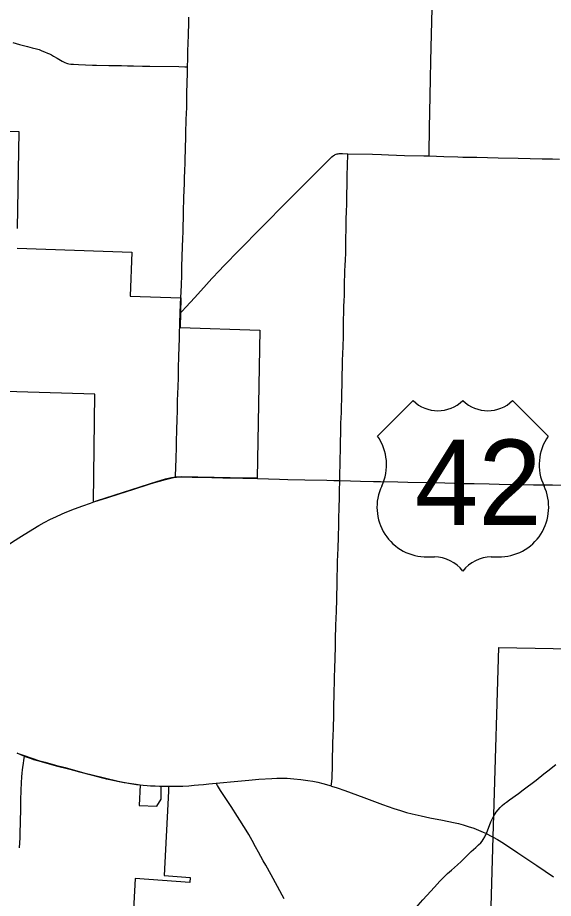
# Model space of a CAD drawing. Extents: x 9078 to 9739, y 4248 to 4966.
# Drawn here: x 9404.5 to 9448.2, y 4627.8 to 4699.7 of the extents above; entities that cross this region are included whole.
import ezdxf

# ---------------------------------------------------------------- set-up
doc = ezdxf.new("R2010")
doc.units = 0
for name, color, linetype in [('GM_X_City_Street', 7, 'Continuous'), ('GM_X_Corporation', 7, 'Continuous'), ('GM_X_County_Road', 7, 'Continuous'), ('GM_X_State_Route', 7, 'Continuous'), ('GM_X_Township', 7, 'Continuous'), ('GM_X_Township_Road', 7, 'Continuous'), ('GM_X_US_Route', 7, 'Continuous'), ('GM_X_US_Shield', 7, 'Continuous')]:
    doc.layers.add(name, color=color, linetype=linetype)

msp = doc.modelspace()

# ---------------------------------------------------------------- linework, layer by layer
at = {"layer": 'GM_X_City_Street'}
for points in [[(9417.378, 4662.149), (9417.388, 4662.384), (9417.402, 4662.847), (9417.411, 4663.16), (9417.421, 4663.477), (9417.431, 4663.815), (9417.448, 4664.48), (9417.453, 4664.688), (9417.463, 4665.075), (9417.486, 4665.984), (9417.512, 4666.884), (9417.532, 4667.539), (9417.553, 4668.439), (9417.566, 4668.93), (9417.609, 4670.239), (9417.626, 4671.058), (9417.653, 4672.04), (9417.669, 4672.777), (9417.693, 4673.513), (9417.711, 4674.167), (9417.72, 4674.388)], [(9404.66, 4631.906), (9404.678, 4632.316), (9404.694, 4632.727), (9404.711, 4633.298), (9404.726, 4633.827), (9404.73, 4634.009), (9404.755, 4635.112), (9404.771, 4635.759), (9404.794, 4636.679), (9404.798, 4636.835), (9404.809, 4636.996), (9404.819, 4637.244), (9404.85, 4637.669), (9404.878, 4638.046), (9404.899, 4638.251), (9404.924, 4638.502), (9404.965, 4638.784), (9405.008, 4639.056), (9405.032, 4639.196), (9405.067, 4639.389)]]:
    msp.add_lwpolyline(points, dxfattribs=at)
at = {"layer": 'GM_X_Corporation'}
for points in [[(9401.571, 4690.474), (9404.598, 4690.369), (9404.461, 4682.443)], [(9404.465, 4680.839), (9413.813, 4680.513), (9413.689, 4676.92), (9417.821, 4676.783), (9417.762, 4674.377), (9424.246, 4674.166), (9424.037, 4662.069), (9423.175, 4662.086), (9419.208, 4662.168), (9417.867, 4662.195), (9417.396, 4662.168), (9417.049, 4662.112), (9416.532, 4661.992), (9416.104, 4661.867), (9415.911, 4661.805), (9410.893, 4660.196), (9410.69, 4660.131), (9410.796, 4668.935), (9402.586, 4669.192)], [(9404.457, 4639.651), (9405.029, 4639.453), (9406.199, 4639.035), (9406.745, 4638.894), (9407.577, 4638.664), (9408.389, 4638.475), (9409.892, 4638.035), (9410.577, 4637.873), (9412.688, 4637.353), (9413.544, 4637.188), (9414.205, 4637.081), (9414.489, 4637.059), (9414.401, 4635.358), (9415.857, 4635.307), (9416.212, 4635.897), (9416.209, 4636.925), (9416.802, 4636.949), (9416.811, 4636.541), (9416.451, 4629.651), (9418.561, 4629.504), (9418.553, 4629.094), (9414.09, 4629.406), (9413.717, 4622.275)]]:
    msp.add_lwpolyline(points, dxfattribs=at)
at = {"layer": 'GM_X_County_Road'}
for points in [[(9438.067, 4688.371), (9438.071, 4688.605), (9438.105, 4690.65), (9438.15, 4693.268), (9438.169, 4694.659), (9438.204, 4696.131), (9438.328, 4701.524)], [(9418.362, 4695.648), (9418.362, 4695.684), (9418.378, 4696.258), (9418.394, 4696.913), (9418.409, 4697.568), (9418.428, 4698.223), (9418.438, 4698.551), (9418.451, 4698.96), (9418.472, 4699.696)], [(9417.814, 4676.793), (9417.856, 4677.821), (9417.882, 4678.641), (9417.9, 4679.297), (9417.929, 4680.197), (9417.975, 4681.673), (9417.991, 4682.165), (9418.008, 4682.738), (9418.022, 4683.23), (9418.031, 4683.737), (9418.036, 4684.223), (9418.044, 4684.553), (9418.051, 4684.818), (9418.061, 4685.039), (9418.074, 4685.508), (9418.105, 4686.178), (9418.121, 4686.67), (9418.135, 4687.08), (9418.161, 4687.899), (9418.195, 4689.129), (9418.213, 4689.784), (9418.232, 4690.44), (9418.252, 4691.096), (9418.26, 4691.423), (9418.269, 4691.751), (9418.288, 4692.405), (9418.3, 4692.815), (9418.309, 4693.553), (9418.329, 4694.291), (9418.353, 4695.192), (9418.362, 4695.648)], [(9417.766, 4675.549), (9417.889, 4675.679), (9418.256, 4676.064), (9418.917, 4676.793), (9419.689, 4677.644), (9420.352, 4678.371), (9420.961, 4679.035), (9421.301, 4679.391), (9421.705, 4679.799), (9422.227, 4680.321), (9422.686, 4680.789), (9423.203, 4681.316), (9423.775, 4681.902), (9424.582, 4682.716), (9425.096, 4683.244), (9425.843, 4684.006), (9426.48, 4684.645), (9427.119, 4685.281), (9427.98, 4686.159), (9428.851, 4687.028), (9430.016, 4688.183), (9430.137, 4688.296), (9430.267, 4688.4), (9430.338, 4688.445), (9430.413, 4688.484), (9430.49, 4688.516), (9430.571, 4688.539), (9430.654, 4688.555), (9430.737, 4688.564), (9430.986, 4688.571), (9431.442, 4688.559)], [(9431.442, 4688.559), (9433.445, 4688.507), (9434.183, 4688.48), (9434.756, 4688.454), (9435.411, 4688.437), (9436.067, 4688.419), (9437.625, 4688.385), (9438.067, 4688.371)], [(9438.067, 4688.371), (9439.264, 4688.334), (9440.412, 4688.29), (9440.821, 4688.277), (9441.969, 4688.263), (9443.691, 4688.218), (9445.331, 4688.181), (9447.299, 4688.149), (9448.118, 4688.127), (9448.692, 4688.118)], [(9417.766, 4675.549), (9417.796, 4676.305), (9417.814, 4676.793)], [(9417.72, 4674.388), (9417.741, 4674.918), (9417.76, 4675.407), (9417.766, 4675.549)], [(9444.377, 4635.653), (9444.613, 4635.833), (9445.345, 4636.363), (9445.743, 4636.652), (9446.07, 4636.898), (9446.458, 4637.198), (9446.784, 4637.447), (9447.432, 4637.952), (9447.754, 4638.206), (9448.404, 4638.706)], [(9443.352, 4634.532), (9443.441, 4634.685), (9443.534, 4634.822), (9443.688, 4635.017), (9443.854, 4635.201), (9444.032, 4635.374), (9444.22, 4635.534), (9444.377, 4635.653)], [(9442.735, 4633.077), (9443.103, 4634.025), (9443.204, 4634.251), (9443.316, 4634.471), (9443.352, 4634.532)]]:
    msp.add_lwpolyline(points, dxfattribs=at)
at = {"layer": 'GM_X_State_Route'}
for points in [[(9404.443, 4639.66), (9404.742, 4639.522), (9405.067, 4639.389), (9405.123, 4639.366), (9405.513, 4639.221), (9405.795, 4639.13), (9406.016, 4639.064), (9406.22, 4639.007), (9407.64, 4638.619), (9408.757, 4638.327), (9409.545, 4638.12), (9410.499, 4637.87), (9411.319, 4637.651), (9411.533, 4637.594), (9411.733, 4637.541), (9412.007, 4637.481), (9412.398, 4637.398), (9412.793, 4637.318), (9413.183, 4637.246), (9413.596, 4637.182), (9414.165, 4637.104), (9414.503, 4637.064)], [(9414.503, 4637.064), (9414.746, 4637.038), (9415.054, 4637.012), (9415.349, 4636.986), (9415.717, 4636.962), (9416.07, 4636.96), (9416.287, 4636.956)], [(9416.834, 4636.947), (9417.082, 4636.947), (9417.411, 4636.952), (9417.988, 4636.957), (9418.477, 4636.986), (9418.905, 4637.017), (9419.252, 4637.047), (9419.651, 4637.087), (9420.099, 4637.132), (9420.691, 4637.193), (9422.455, 4637.353), (9423.354, 4637.44), (9424.171, 4637.511), (9425.235, 4637.587), (9425.645, 4637.603), (9426.056, 4637.604), (9426.467, 4637.589), (9426.493, 4637.588)], [(9426.493, 4637.588), (9427.04, 4637.548), (9427.612, 4637.491), (9428.182, 4637.416), (9428.587, 4637.347), (9428.989, 4637.262), (9429.387, 4637.161), (9430.079, 4636.965), (9430.098, 4636.959), (9430.569, 4636.815), (9431.189, 4636.596), (9432.729, 4636.03), (9434.266, 4635.457), (9435.192, 4635.126), (9435.737, 4634.949), (9436.208, 4634.811), (9436.684, 4634.691), (9437.403, 4634.528), (9438.125, 4634.373), (9439.17, 4634.163), (9440.055, 4633.986), (9440.455, 4633.893), (9440.852, 4633.788), (9441.246, 4633.669), (9441.712, 4633.51), (9442.096, 4633.363), (9442.474, 4633.202), (9442.735, 4633.077), (9442.771, 4633.06), (9443.135, 4632.87), (9443.303, 4632.776), (9443.636, 4632.588), (9444.125, 4632.287), (9445.29, 4631.52), (9446.855, 4630.47), (9448.207, 4629.542)], [(9416.287, 4636.956), (9416.491, 4636.953), (9416.695, 4636.95), (9416.834, 4636.947)]]:
    msp.add_lwpolyline(points, dxfattribs=at)
at = {"layer": 'GM_X_Township'}
msp.add_lwpolyline([(9449.713, 4567.764), (9447.057, 4567.406), (9441.547, 4566.662), (9441.81, 4581.702), (9443.285, 4632.801), (9443.341, 4634.62), (9443.761, 4648.254), (9457.059, 4648.02)], dxfattribs=at)
at = {"layer": 'GM_X_Township_Road'}
for points in [[(9404.1, 4697.625), (9404.649, 4697.459), (9404.982, 4697.372), (9405.312, 4697.294), (9405.684, 4697.206), (9406.037, 4697.116), (9406.254, 4697.046), (9406.48, 4696.96), (9406.688, 4696.873), (9406.944, 4696.764), (9407.097, 4696.693), (9407.257, 4696.612), (9407.427, 4696.519), (9407.726, 4696.339), (9408.119, 4696.11), (9408.342, 4696.002), (9408.477, 4695.948), (9408.577, 4695.918), (9408.681, 4695.892), (9408.833, 4695.87), (9409.066, 4695.852), (9409.474, 4695.828), (9410.618, 4695.778), (9410.945, 4695.772), (9411.926, 4695.767), (9412.333, 4695.762), (9412.656, 4695.752), (9412.982, 4695.74), (9413.461, 4695.727), (9413.962, 4695.713), (9414.698, 4695.707), (9415.271, 4695.701), (9417.646, 4695.662), (9418.137, 4695.652), (9418.362, 4695.648)], [(9430.778, 4661.877), (9430.781, 4661.92), (9430.786, 4662.236), (9430.805, 4663.398), (9430.831, 4664.628), (9430.84, 4665.121), (9430.85, 4665.694), (9430.856, 4665.94), (9430.876, 4666.513), (9430.895, 4667.054), (9430.906, 4667.379), (9430.918, 4667.731), (9430.954, 4668.728), (9430.979, 4670.041), (9431.009, 4671.594), (9431.03, 4672.306), (9431.047, 4672.749), (9431.07, 4673.734), (9431.085, 4674.718), (9431.091, 4675.128), (9431.095, 4675.456), (9431.113, 4676.111), (9431.132, 4676.535), (9431.149, 4677.012), (9431.158, 4677.272), (9431.166, 4677.833), (9431.203, 4678.981), (9431.228, 4679.472), (9431.248, 4679.882), (9431.258, 4680.456), (9431.258, 4680.702), (9431.262, 4681.275), (9431.271, 4681.686), (9431.285, 4682.342), (9431.295, 4682.751), (9431.311, 4683.243), (9431.327, 4683.818), (9431.342, 4684.474), (9431.361, 4685.294), (9431.375, 4685.95), (9431.391, 4686.77), (9431.408, 4687.591), (9431.441, 4688.52), (9431.442, 4688.559)], [(9430.079, 4636.965), (9430.097, 4637.114), (9430.124, 4637.349), (9430.146, 4637.595), (9430.162, 4637.924), (9430.171, 4638.335), (9430.179, 4638.826), (9430.194, 4639.48), (9430.204, 4639.889), (9430.206, 4640.217), (9430.214, 4640.456), (9430.224, 4640.699), (9430.23, 4640.843), (9430.244, 4641.073), (9430.265, 4641.628), (9430.27, 4642.016), (9430.279, 4642.427), (9430.29, 4643.001), (9430.301, 4643.739), (9430.31, 4644.15), (9430.316, 4644.477), (9430.321, 4644.804), (9430.334, 4645.292), (9430.349, 4645.699), (9430.36, 4646.026), (9430.371, 4646.354), (9430.385, 4646.764), (9430.396, 4647.174), (9430.405, 4647.582), (9430.418, 4648.151), (9430.428, 4648.639), (9430.439, 4649.211), (9430.453, 4649.784), (9430.465, 4650.111), (9430.482, 4650.603), (9430.501, 4651.26), (9430.528, 4652.162), (9430.541, 4652.654), (9430.551, 4653.147), (9430.57, 4654.049), (9430.583, 4654.705), (9430.601, 4655.278), (9430.62, 4655.827), (9430.639, 4656.37), (9430.662, 4657.264), (9430.689, 4658.311), (9430.702, 4658.887), (9430.719, 4659.543), (9430.749, 4660.609), (9430.762, 4661.266), (9430.772, 4661.65), (9430.778, 4661.877)], [(9426.231, 4627.759), (9426.082, 4628.052), (9425.686, 4628.771), (9425.171, 4629.705), (9424.735, 4630.495), (9424.538, 4630.855), (9424.145, 4631.575), (9423.911, 4632.008), (9423.633, 4632.51), (9423.346, 4633.008), (9423.133, 4633.358), (9422.434, 4634.47), (9421.905, 4635.3), (9421.051, 4636.605), (9420.805, 4637.001), (9420.691, 4637.193)], [(9441.41, 4631.531), (9441.495, 4631.614), (9441.863, 4631.943), (9442.106, 4632.162), (9442.276, 4632.337), (9442.38, 4632.461), (9442.474, 4632.593), (9442.6, 4632.803), (9442.647, 4632.886), (9442.686, 4632.965), (9442.735, 4633.077)], [(9436.54, 4626.488), (9436.7, 4626.673), (9437.183, 4627.233), (9437.56, 4627.665), (9437.887, 4628.034), (9438.492, 4628.703), (9438.939, 4629.185), (9439.281, 4629.54), (9439.576, 4629.826), (9439.88, 4630.101), (9440.373, 4630.533), (9440.674, 4630.81), (9441.084, 4631.212), (9441.41, 4631.531)]]:
    msp.add_lwpolyline(points, dxfattribs=at)
at = {"layer": 'GM_X_US_Route'}
for points in [[(9410.714, 4660.136), (9411.852, 4660.499), (9412.791, 4660.801), (9413.968, 4661.172), (9415.142, 4661.552), (9415.672, 4661.727), (9416.167, 4661.874), (9416.559, 4661.984), (9416.884, 4662.065), (9417.204, 4662.125), (9417.378, 4662.149), (9417.45, 4662.159), (9417.698, 4662.178), (9418.11, 4662.184), (9418.723, 4662.171)], [(9418.723, 4662.171), (9419.509, 4662.155), (9420.331, 4662.132), (9421.236, 4662.112), (9422.88, 4662.069), (9424.055, 4662.044)], [(9424.055, 4662.044), (9425.871, 4661.994), (9426.529, 4661.984), (9427.925, 4661.947), (9429.733, 4661.905), (9430.289, 4661.893), (9430.474, 4661.889), (9430.778, 4661.877), (9431.649, 4661.864), (9432.47, 4661.84), (9433.535, 4661.808), (9434.109, 4661.797), (9435.504, 4661.773), (9436.324, 4661.754), (9437.883, 4661.717), (9439.359, 4661.69), (9440.097, 4661.673), (9440.835, 4661.656), (9441.737, 4661.636), (9442.967, 4661.619), (9443.787, 4661.597), (9445.674, 4661.563), (9446.577, 4661.547), (9448.135, 4661.532), (9448.956, 4661.518)], [(9400.383, 4654.531), (9401.511, 4655.248), (9402.063, 4655.604), (9403.124, 4656.276), (9403.585, 4656.568), (9404.303, 4657.023), (9404.588, 4657.203), (9404.826, 4657.354), (9405.732, 4657.928), (9406.226, 4658.221), (9406.657, 4658.459), (9407.167, 4658.722), (9407.611, 4658.935), (9408.136, 4659.17), (9408.513, 4659.332), (9409.126, 4659.57), (9409.818, 4659.828), (9410.438, 4660.044), (9410.714, 4660.136)]]:
    msp.add_lwpolyline(points, dxfattribs=at)
at = {"layer": 'GM_X_US_Shield'}
for p, q in [((9436.756, 4668.413), (9433.856, 4665.513)), ((9447.777, 4665.513), (9444.877, 4668.413)), ((9437.916, 4655.651), (9438.496, 4655.651)), ((9443.137, 4655.651), (9443.717, 4655.651))]:
    msp.add_line(p, q, dxfattribs=at)
for centre, radius, start, end in [((9438.786, 4670.484), 2.9, 225.573, 314.427), ((9442.847, 4670.484), 2.9, 225.573, 314.427), ((9430.529, 4663.184), 4.061, 334.54712, 35.00093), ((9451.104, 4663.184), 4.061, 144.99907, 205.45288), ((9437.871, 4659.712), 4.061, 154.83192, 270.63826), ((9443.762, 4659.712), 4.061, 269.36174, 25.16808), ((9438.496, 4652.751), 2.9, 36.8699, 90), ((9443.137, 4652.751), 2.9, 90, 143.1301)]:
    msp.add_arc(centre, radius, start, end, dxfattribs=at)

# ---------------------------------------------------------------- texts
msp.add_text('42', height=6.961, dxfattribs=at).set_placement((9436.898, 4658.262))

doc.saveas('drawing.dxf')
